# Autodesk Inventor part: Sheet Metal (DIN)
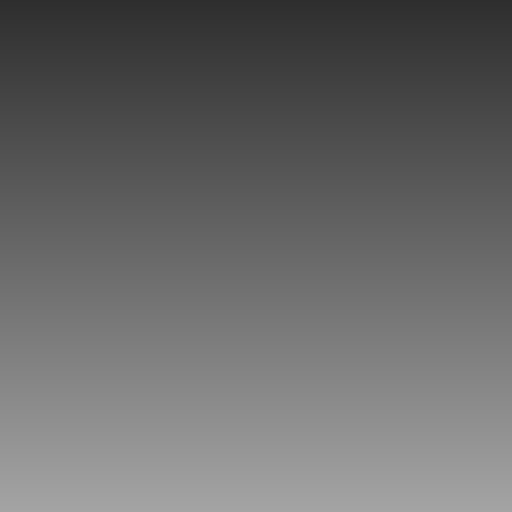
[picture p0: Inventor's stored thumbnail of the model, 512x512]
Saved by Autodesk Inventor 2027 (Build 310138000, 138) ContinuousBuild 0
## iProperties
Shininess: 64.0
Length Units: 11269
Angle Units: 11279
Time Units: 11290
Mass Units: 11283
Length Display Precision: 3
Angle Display Precision: 2
Compacted: True
Part Number: Sheet Metal (DIN)
Document SubType Name: Sheet Metal
Created: 2002-07
Material: Generic
Density: 1 g/cm^3
Sheet Metal Rule: Default_mm
Appearance: Default
Density: 0.0
Volumn: 0.0
Area: 0.0
PropertySet Name: Model Information
Control State: 0
Master: False
Checked Out: False
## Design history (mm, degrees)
other parameters: "Thickness" = 0.5, "BendRadius" = 0.5 (= Thickness), "BendReliefWidth" = 0.5 (= Thickness), "BendReliefDepth" = 0.25 (= 0.5 x Thickness), "CornerReliefSize" = 2 (= 4 x Thickness), "SeamGap" = 0.01, "MinimumRemnant" = 1 (= 2 x Thickness), "TransitionRadius" = 0.5 (= BendRadius), "JacobiRadiusSize" = 0.5 (= BendRadius), "GapSize" = 0.5 (= Thickness)
